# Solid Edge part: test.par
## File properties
Title: Solid Edge 20
Author: vicky raina
Template: Normal.par
Last saved by: Robert a Rhodes jr
Revision: 8
Application: Solid Edge
Material: aluminum
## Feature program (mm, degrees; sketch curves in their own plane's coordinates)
sketch for "unnamed RevolvedProtrusion 1" plane through (0, 0, 0) normal (0, -1, 0) x-axis (1, 0, 0)
  line (47.625, 16.8036) -> (66.929, 16.8036)
  line (66.929, 16.8036) -> (73.025, 10.7076)
  line (73.025, 10.7076) -> (73.025, -12.0254)
  line (73.025, -12.0254) -> (66.929, -18.1214)
  line (66.929, -18.1214) -> (47.625, -18.1214)
  line (47.625, -18.1214) -> (47.625, -7.1994)
  line (61.5714, -7.1994) -> (47.625, -7.1994)
  line (61.5714, 5.8816) -> (61.5714, -7.1994)
  line (47.625, 5.8816) -> (61.5714, 5.8816)
  line (47.625, 5.8816) -> (47.625, 16.8036)
revolve "unnamed RevolvedProtrusion 1" add finite 360 deg
sketch for "unnamed RevolvedProtrusion 2" plane through (0, 0, 0) normal (1, 0, 0) x-axis (0, 1, 0)
  line (69.977, 13.7556) -> (73.0652, 13.7556)
  line (73.0652, 13.7556) -> (74.6125, 12.2083)
  line (74.6125, 12.2083) -> (74.6125, -13.4669)
  line (74.6125, -13.4669) -> (73.006, -15.0734)
  line (73.006, -15.0734) -> (69.977, -15.0734)
revolve "unnamed RevolvedProtrusion 2" add full turn 360 deg
sketch for "unnamed RevolvedProtrusion 3" plane through (0, 0, 0) normal (0, -1, 0) x-axis (1, 0, 0)
revolve "unnamed RevolvedProtrusion 3" add full turn 360 deg about sketch line (-54.9674, 10.1232) -> (-54.9674, -18.1214)
pattern "unnamed Pattern 1" of "unnamed RevolvedProtrusion 3"
pattern "unnamed Pattern 2"
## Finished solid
Body 1: solid body, 39 faces, 39 edges, 25 vertices.
  Faces by surface: torus 25, plane 6, cone 4, cylinder 4
  Edges by curve: circle 39
Bounding box of the edges (mm; curved faces can reach further): 149.225 x 149.225 x 34.925, from (-74.6125, -74.6125, -18.1214) to (74.6125, 74.6125, 16.8036).
Cylindrical faces by radius (mm): R47.625 x2, R61.5714 x1, R74.6125 x1
Conical faces (half-angle, radius in mm at the cone's reference point): 45 deg R66.929 x1, 45 deg R73.025 x1, 45 deg R73.0652 x1, 45 deg R74.6125 x1
Toroidal faces (ring radius, tube radius in mm): R-0.1023 r6.604 x25
Planar faces by outward normal: +z 3, -z 3
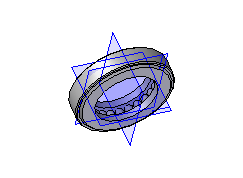
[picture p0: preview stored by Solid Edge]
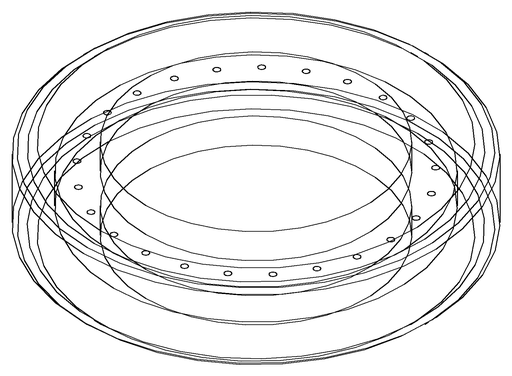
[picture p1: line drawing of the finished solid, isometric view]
